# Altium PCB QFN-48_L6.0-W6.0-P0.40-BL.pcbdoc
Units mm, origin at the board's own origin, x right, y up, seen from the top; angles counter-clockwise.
Board outline 19.88 x 19.5 mm, 2 copper layers (Top Layer, Bottom Layer); 1 components, 0 nets, 49 pads, 16 vias.
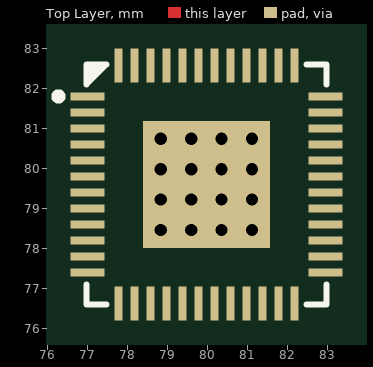
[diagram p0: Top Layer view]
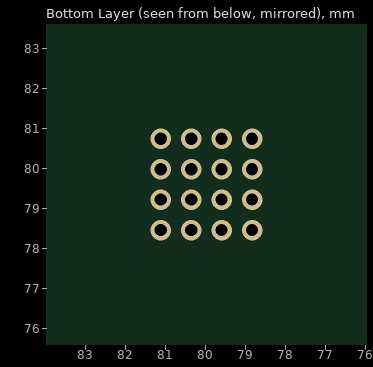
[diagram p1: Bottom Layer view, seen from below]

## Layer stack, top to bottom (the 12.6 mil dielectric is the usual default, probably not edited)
Top Layer: signal copper (thickness not stored)
Dielectric: dielectric 0.32, FR-4, Dk 4.8
Bottom Layer: signal copper (thickness not stored)

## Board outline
89.726,69.85 69.85,69.85 69.85,89.35 89.726,89.35

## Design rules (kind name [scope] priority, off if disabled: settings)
BoardOutlineClearance safeClearance [All] p0: genericclearance=0.254 ignorepadtopadclearanceinfootprint=FALSE except(0: Arc-SplitContinuation Track-SplitContinuation SMDPad-SplitContinuation THPad-SplitContinuation Via-SplitContinuation Fill-SplitContinuation Poly-SplitContinuation Region-SplitContinuation Text-SplitContinuation; 0.152: Track-CutoutEdge SMDPad-CutoutEdge THPad-CutoutEdge Via-CutoutEdge Fill-CutoutEdge Region-CutoutEdge; 0.3: Track-OutlineEdge SMDPad-OutlineEdge THPad-OutlineEdge Via-OutlineEdge Fill-OutlineEdge Region-OutlineEdge Poly-OutlineEdge Text-OutlineEdge)
Clearance safeClearance [All] p1: gap=0.178 ignorepadtopadclearanceinfootprint=FALSE except(0.152: Track-Track Track-SMDPad SMDPad-SMDPad Track-THPad SMDPad-THPad THPad-THPad Track-Via SMDPad-Via THPad-Via Via-Via Track-Fill SMDPad-Fill THPad-Fill Via-Fill Fill-Fill Track-Region SMDPad-Region THPad-Region Via-Region Fill-Region Region-Region Track-Poly SMDPad-Poly THPad-Poly Via-Poly Fill-Poly Region-Poly Poly-Poly Track-Text SMDPad-Text THPad-Text Via-Text Fill-Text Region-Text Poly-Text Text-Text Track-Hole SMDPad-Hole THPad-Hole Via-Hole Fill-Hole Region-Hole Poly-Hole Text-Hole; 0.3: Track-Sheet SMDPad-Sheet THPad-Sheet Via-Sheet Fill-Sheet Region-Sheet Poly-Sheet Text-Sheet Sheet-Hole)
DiffPairsRouting differentialPair [All] p1: maxuncoupledlength=10 minlimit=6 maxlimit=6 mostfreqgap=6 toplayer_minwidth=5 toplayer_prefwidth=10 toplayer_maxwidth=100 bottomlayer_minwidth=5 bottomlayer_prefwidth=10 bottomlayer_maxwidth=100
PasteMaskExpansion pasteMaskExpansion [All] p1: expansion=0
PlaneConnect innerPlane [All] p1: planeconnectstyle=Relief reliefexpansion=0.508 reliefentries=4 reliefconductorwidth=0.254 reliefairgap=0.254
PolygonConnect copperRegion [All] p1: connectstyle=Relief reliefentries=4 reliefconductorwidth=10 polygonreliefangle="90 Angle" airgapwidth=10
RoutingVias viaSize [All] p1: viastyle="Through Hole" holewidth=12.0078 minholewidth=11.811 maxholewidth=236.2204 width=24.0158 minwidth=19.685 maxwidth=393.7008
SolderMaskExpansion solderMaskExpansion [All] p1: useseparateexpansions=TRUE expansion=4 expansionbottom=4
Width trackWidth [All] p1: maxlimit=100 minlimit=5 preferedwidth=10

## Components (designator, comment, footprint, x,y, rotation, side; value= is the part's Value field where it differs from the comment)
? "QFN-48_L6.0-W6.0-P0.40-BL-EP3.17" QFN-48_L6.0-W6.0-P0.40-BL-EP3.17 79.976,79.6 r0 top

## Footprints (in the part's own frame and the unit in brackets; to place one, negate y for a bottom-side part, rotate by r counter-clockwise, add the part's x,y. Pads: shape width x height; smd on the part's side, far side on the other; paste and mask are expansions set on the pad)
QFN-48_L6.0-W6.0-P0.40-BL-EP3.17 [mm]
  rect 0.85x0.2 smd: 1(-2.975,2.2) 2(-2.975,1.8) 3(-2.975,1.4) 4(-2.975,1) 5(-2.975,0.6) 6(-2.975,0.2) 7(-2.975,-0.2) 8(-2.975,-0.6) 9(-2.975,-1) 10(-2.975,-1.4) 11(-2.975,-1.8) 12(-2.975,-2.2) 25(2.975,-2.2) 26(2.975,-1.8) 27(2.975,-1.4) 28(2.975,-1) 29(2.975,-0.6) 30(2.975,-0.2) 31(2.975,0.2) 32(2.975,0.6) 33(2.975,1) 34(2.975,1.4) 35(2.975,1.8) 36(2.975,2.2)
  rect 0.2x0.85 smd: 13(-2.2,-2.975) 14(-1.8,-2.975) 15(-1.4,-2.975) 16(-1,-2.975) 17(-0.6,-2.975) 18(-0.2,-2.975) 19(0.2,-2.975) 20(0.6,-2.975) 21(1,-2.975) 22(1.4,-2.975) 23(1.8,-2.975) 24(2.2,-2.975) 37(2.2,2.975) 38(1.8,2.975) 39(1.4,2.975) 40(1,2.975) 41(0.6,2.975) 42(0.2,2.975) 43(-0.2,2.975) 44(-0.6,2.975) 45(-1,2.975) 46(-1.4,2.975) 47(-1.8,2.975) 48(-2.2,2.975)
  rect 3.17x3.17 smd: 49(0,0)
  silkscreen extent -3.78,-3 3,3.01

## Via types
v1: diameter 0.508, hole 0.305, Top Layer to Bottom Layer, 16 vias

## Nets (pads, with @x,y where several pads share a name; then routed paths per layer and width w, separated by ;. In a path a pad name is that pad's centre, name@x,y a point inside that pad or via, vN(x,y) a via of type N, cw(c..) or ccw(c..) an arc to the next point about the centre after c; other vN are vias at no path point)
pads on no net: ?.1 ?.2 ?.3 ?.4 ?.5 ?.6 ?.7 ?.8 ?.9 ?.10 ?.11 ?.12 ?.13 ?.14 ?.15 ?.16 ?.17 ?.18 ?.19 ?.20 ?.21 ?.22 ?.23 ?.24 ?.25 ?.26 ?.27 ?.28 ?.29 ?.30 ?.31 ?.32 ?.33 ?.34 ?.35 ?.36 ?.37 ?.38 ?.39 ?.40 ?.41 ?.42 ?.43 ?.44 ?.45 ?.46 ?.47 ?.48 ?.49
copper on no net:
  other v1: 78.833,78.457 79.595,78.457 80.357,78.457 81.119,78.457 78.833,79.219 79.595,79.219 80.357,79.219 81.119,79.219 78.833,79.981 79.595,79.981 80.357,79.981 81.119,79.981 78.833,80.743 79.595,80.743 80.357,80.743 81.119,80.743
